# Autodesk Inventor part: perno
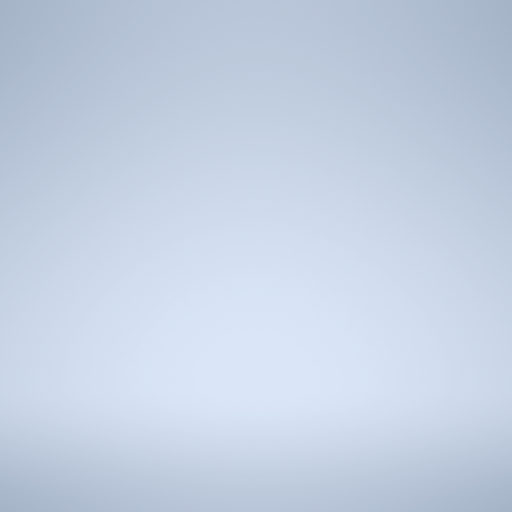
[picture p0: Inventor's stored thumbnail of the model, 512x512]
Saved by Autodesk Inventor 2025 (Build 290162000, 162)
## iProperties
Created: 2025-10
Part Number: perno
Material: Generico
Document SubType Name: Modeling
Designer: 18619647
Density: 1 g/cm^3
Appearance: Default
Author: 18619647
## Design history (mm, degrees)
